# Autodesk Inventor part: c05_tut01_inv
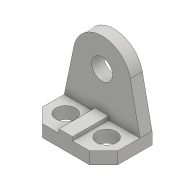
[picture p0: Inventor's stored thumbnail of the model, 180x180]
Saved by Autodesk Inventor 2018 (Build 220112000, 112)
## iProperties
Created: 2017-04
Part Number: c05_tut01_inv
Material: Generic
Document SubType Name: Modeling
Designer: CADCIM 00
Density: 1 g/cm^3
Appearance: Default
Author: CADCIM 00
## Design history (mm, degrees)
sketch "Sketch1"
  geometry: L1 (0, 0)-(-200, 0); L2 (-200, 0)-(-200, -90); L3 (-200, -90)-(-162, -128); L4 (-162, -128)-(-38, -128); L5 (-38, -128)-(0, -90); L6 (0, -90)-(0, 0); L7 (-200, -90)-(0, -90); C1 r 26 at (-154, -74); C2 r 26 at (-46, -74)
  constraints: 14 end point, 3 horizontal, 3 perpendicular, 2 centre point, 1 equal radius, 1 horizontal alignment
  dimensions: "d0" = 90 distance of L1.end L2.end; "d1" = 128 distance between parallel lines of L1 L4; "d2" = 38 distance from line of L3.end L2; "d3" = 124 distance of L3.end L4.end; "d4" = 46 distance from line of L2 C1.centre; "d5" = 74 distance from line of L1 C1.centre; "d6" = 52 diameter of C1; "d7" = 46 distance from line of L6 C2.centre
extrude "Extrusion1" new body sketch "Sketch1" distance "d8" = 32; taper "d9" = 0 deg
sketch "Sketch2"
  geometry: L1 (200, -32)-(0, -32) reference; L2 (200, -32)-(174.418, -155.424); L3 (25.582, -155.424)-(0, -32); L4 (0, -32)-(200, -32); L5 (100, -32)-(100, -140); C1 r 27.5 at (100, -140); A1 r 76 centre (100, -140) between (25.582, -155.424) and (174.418, -155.424); 1 further point
  constraints: 8 end point, 2 centre point, 2 point on circle, 2 tangent, 1 coincident, 1 collinear, 1 midpoint, 1 vertical
  dimensions: "d10" = 55 diameter of C1; "d11" = 76 radius of A1; "d12" = 108 distance from line of L1 A1.centre
extrude "Extrusion2" join sketch "Sketch2" distance "d13" = 32; taper "d14" = 0 deg
sketch "Sketch3"
  geometry: L1 (82, 42)-(118, 42); L2 (118, 42)-(118, 32); L3 (118, 32)-(82, 32); L4 (82, 32)-(82, 42); L5 (38, 32)-(162, 32) reference; L6 (0, 0)-(0, 32) reference; 1 further point
  constraints: 8 end point, 2 parallel, 1 collinear, 1 horizontal, 1 perpendicular
  dimensions: "d15" = 10 distance between parallel lines of L3 L1; "d16" = 36 distance of L1.start L1.end; "d17" = 82 distance from line of L6 L1.start
extrude "Extrusion3" join sketch "Sketch3" stored distance "d18" = 32; taper "d19" = 0 deg
body "Solid1"
